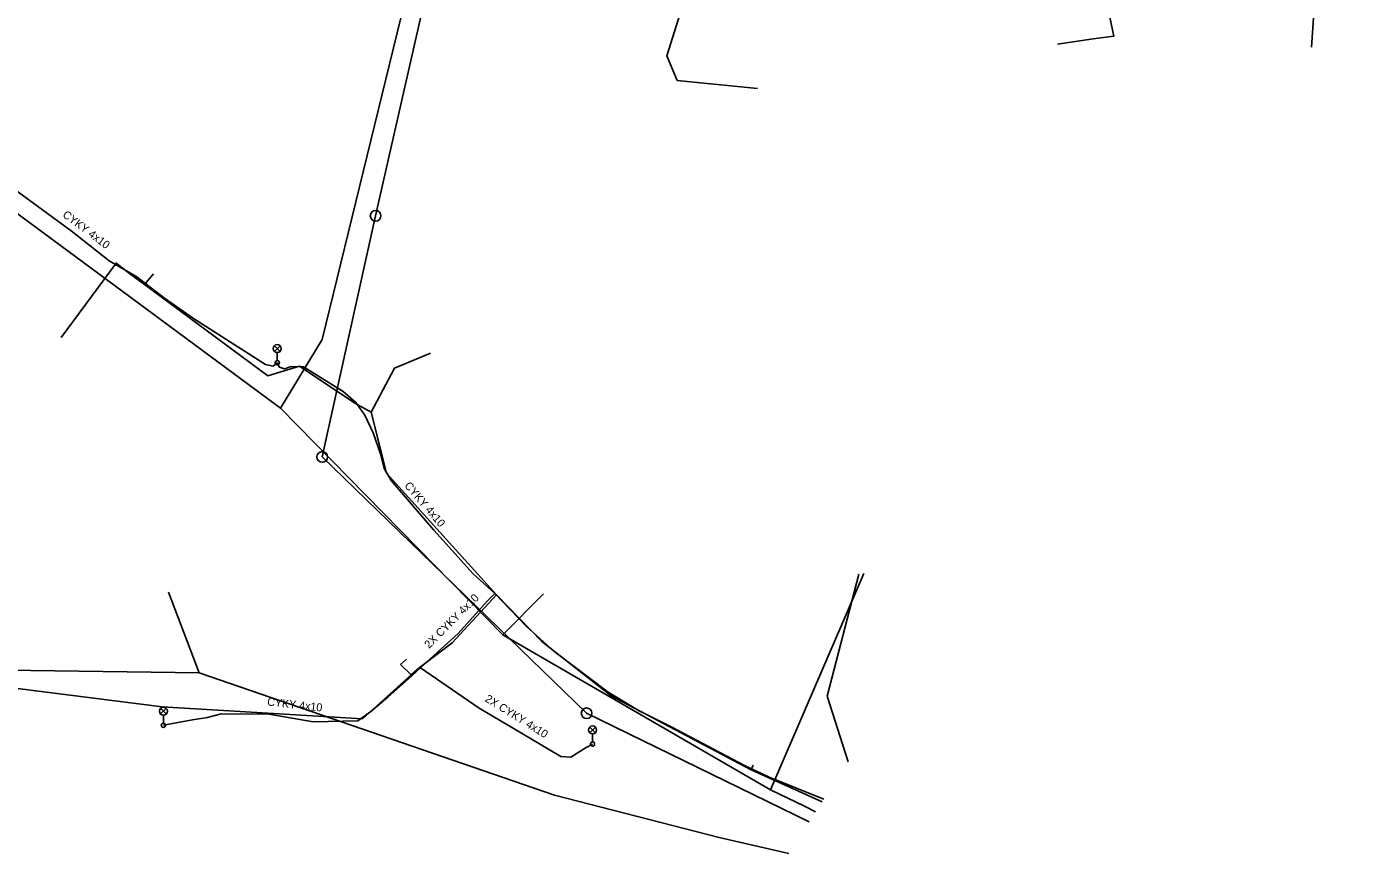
# Model space of a CAD drawing. Extents: x -737422 to -734235, y -1145631 to -1142623.
# Drawn here: x -736944.2 to -736819.2, y -1144919.8 to -1144842.3 of the extents above; entities that cross this region are included whole.
import ezdxf

# ---------------------------------------------------------------- set-up
doc = ezdxf.new("R2010")
doc.units = 0
for name, color, linetype in [('Vrstva 1', 7, 'Continuous'), ('Vrstva 19', 7, 'Continuous'), ('Vrstva 20', 7, 'Continuous'), ('Vrstva 34', 7, 'Continuous'), ('Vrstva 40', 7, 'Continuous'), ('Vrstva 41', 7, 'Continuous'), ('Vrstva 44', 7, 'Continuous'), ('Vrstva 48', 7, 'Continuous')]:
    doc.layers.add(name, color=color, linetype=linetype)

# ---------------------------------------------------------------- blocks, each defined once
blk = doc.blocks.new('6.200')
at = {"layer": 'Vrstva 1'}
blk.add_circle((0, 0), 1, dxfattribs=at)
blk = doc.blocks.new('6.560')
at = {"layer": 'Vrstva 1'}
for p, q in [((-0.528, 2.124), (0.528, 3.18)), ((0.544, 2.13), (-0.512, 3.188)), ((0, 1.9), (0, 0.4))]:
    blk.add_line(p, q, dxfattribs=at)
for centre, radius in [((0, 2.65), 0.75), ((0, 0), 0.4)]:
    blk.add_circle(centre, radius, dxfattribs=at)

msp = doc.modelspace()

# ---------------------------------------------------------------- linework, layer by layer
at = {"layer": 'Vrstva 1'}
for points in [[(-736875.7, -1144848.09), (-736883.22, -1144847.33), (-736884.18, -1144845.02), (-736876.97, -1144822.08), (-736876.39, -1144819.98), (-736870.6, -1144821.45), (-736863.03, -1144825.56), (-736858.71, -1144827.79), (-736849.16, -1144832.72), (-736846.17, -1144833.48), (-736843.72, -1144834.58)], [(-736843.72, -1144834.58), (-736843.93, -1144835.43), (-736842.3, -1144843.17), (-736844.25, -1144843.44), (-736847.59, -1144843.92)], [(-736823.778, -1144844.217), (-736823.57, -1144841.04)], [(-736933.14, -1144866.48), (-736934.55, -1144865.44), (-736935.81, -1144864.47), (-736940.97, -1144871.44)], [(-736933.14, -1144866.48), (-736932.31, -1144865.46)], [(-736933.14, -1144866.48), (-736921.6, -1144875.04), (-736918.63, -1144874.14), (-736913.42, -1144877.6), (-736911.92, -1144878.46)], [(-736906.33, -1144872.92), (-736909.73, -1144874.33), (-736911.92, -1144878.46)], [(-736911.92, -1144878.46), (-736910.46, -1144884.17), (-736900.17, -1144895.59)], [(-737067.53, -1144887.62), (-737044.25, -1144894.43), (-737027.71, -1144897.68), (-737007.28, -1144902), (-736994.61, -1144902.63), (-736992.92, -1144905.3), (-736982.45, -1144906.21), (-736972.84, -1144905.66), (-736969.04, -1144902.9), (-736965.15, -1144901.63), (-736959.3, -1144902.83), (-736956.18, -1144902.96), (-736931.49, -1144906.08), (-736912.72, -1144907.2), (-736908.17, -1144903.08)], [(-736866.19, -1144893.65), (-736869.17, -1144905.1), (-736867.202, -1144911.242)], [(-736928.01, -1144902.9), (-736930.89, -1144895.33)], [(-736900.17, -1144895.59), (-736904.3, -1144900.08), (-736907.41, -1144902.42)], [(-736876.28, -1144912.01), (-736889.41, -1144905.05), (-736895.9, -1144899.97), (-736900.17, -1144895.59)], [(-736928.01, -1144902.9), (-736959.61, -1144902.46), (-736964.22, -1144901.19)], [(-736909.15, -1144902.11), (-736908.59, -1144901.623)], [(-736908.17, -1144903.08), (-736909.15, -1144902.11)], [(-736872.766, -1144919.83), (-736879.28, -1144918.33), (-736894.72, -1144914.36), (-736928.01, -1144902.9)], [(-736907.41, -1144902.42), (-736908.17, -1144903.08)], [(-736876.28, -1144912.01), (-736876.1, -1144911.57)], [(-736876.28, -1144912.01), (-736869.641, -1144915.007)]]:
    msp.add_lwpolyline(points, dxfattribs=at)
at = {"layer": 'Vrstva 19'}
for points in [[(-736874.47, -1144913.86), (-736865.72, -1144893.59)], [(-736895.76, -1144895.49), (-736899.56, -1144899.32)]]:
    msp.add_lwpolyline(points, dxfattribs=at)
at = {"layer": 'Vrstva 20'}
for points in [[(-736920.4, -1144878.06), (-736972.09, -1144839.84), (-737043.15, -1144791.09), (-737078.91, -1144779.06), (-737081, -1144796.97)], [(-736920.4, -1144878.06), (-736916.51, -1144871.64), (-736906.66, -1144831.34), (-736899.59, -1144823.06), (-736888.63, -1144818.43), (-736854.34, -1144829.36), (-736819.202, -1144837.154)], [(-736870.249, -1144915.944), (-736871.28, -1144915.42), (-736874.47, -1144913.86), (-736899.56, -1144899.32), (-736920.4, -1144878.06)]]:
    msp.add_lwpolyline(points, dxfattribs=at)
at = {"layer": 'Vrstva 34'}
for points in [[(-736959.42, -1144847.54), (-736959.41, -1144848.11), (-736959.06, -1144848.64), (-736956.31, -1144850.37), (-736952.75, -1144852.39), (-736945.73, -1144857.24), (-736940.03, -1144861.45), (-736936.47, -1144864.25), (-736933.86, -1144865.77), (-736931.28, -1144867.75), (-736928.55, -1144869.68), (-736921.8, -1144873.97), (-736921.08, -1144874.14), (-736920.71, -1144873.81)], [(-736920.71, -1144873.81), (-736920.49, -1144874.23), (-736920.04, -1144874.38), (-736919.4, -1144874.16), (-736918.24, -1144874.19), (-736914.52, -1144876.51), (-736913.33, -1144877.53), (-736912.49, -1144878.72), (-736911.71, -1144880.38), (-736910.99, -1144882.46), (-736910.69, -1144883.72), (-736910.02, -1144884.86), (-736906.03, -1144889.52), (-736902.33, -1144893.6), (-736900.32, -1144895.45)], [(-736907.27, -1144902.43), (-736906.36, -1144901.6), (-736903.74, -1144899.22), (-736901.04, -1144896.19), (-736900.32, -1144895.45)], [(-736900.32, -1144895.45), (-736897.38, -1144898.53), (-736894.77, -1144900.86), (-736889.69, -1144904.72), (-736886.79, -1144906.45), (-736883.74, -1144908), (-736876.93, -1144911.59), (-736874.61, -1144912.67), (-736869.47, -1144914.742)], [(-736931.38, -1144907.82), (-736928.66, -1144907.3), (-736927.25, -1144907.09), (-736925.96, -1144906.73), (-736921.46, -1144906.77), (-736917.33, -1144907.49), (-736913.17, -1144907.4), (-736911.94, -1144906.51), (-736910.31, -1144905.14), (-736908.41, -1144903.47), (-736907.27, -1144902.43)], [(-736891.16, -1144909.58), (-736891.75, -1144909.89), (-736893.18, -1144910.81), (-736894.14, -1144910.75), (-736898.66, -1144908.06), (-736901.78, -1144906.21), (-736907.27, -1144902.43)]]:
    msp.add_lwpolyline(points, dxfattribs=at)
at = {"layer": 'Vrstva 40'}
for points in [[(-736911.49, -1144860.04), (-736906.81, -1144839.39), (-736905.38, -1144833.05), (-736900.7, -1144812.4)], [(-736916.49, -1144882.65), (-736911.49, -1144860.04)], [(-736891.71, -1144906.69), (-736916.49, -1144882.65)], [(-736870.851, -1144916.873), (-736891.71, -1144906.69)]]:
    msp.add_lwpolyline(points, dxfattribs=at)

# ---------------------------------------------------------------- block references
at = {"layer": 'Vrstva 41', "xscale": 0.5, "yscale": 0.5}
for p in [(-736911.49, -1144860.04), (-736916.49, -1144882.65), (-736891.71, -1144906.69)]:
    msp.add_blockref('6.200', p, dxfattribs=at)
at = {"layer": 'Vrstva 44', "xscale": 0.5, "yscale": 0.5}
for p in [(-736920.71, -1144873.81), (-736931.38, -1144907.82), (-736891.16, -1144909.58)]:
    msp.add_blockref('6.560', p, dxfattribs=at)

# ---------------------------------------------------------------- texts
at = {"layer": 'Vrstva 48'}
for s, rotation, p in [('CYKY 4x10', 322.995, (-736940.89, -1144860.07)), ('CYKY 4x10', 310.655, (-736908.84, -1144885.37)), ('2X CYKY 4x10', 44.917, (-736906.48, -1144900.67)), ('CYKY 4x10', 353.614, (-736921.68, -1144905.96)), ('2X CYKY 4x10', 328.121, (-736901.31, -1144905.52))]:
    msp.add_text(s, height=0.75, rotation=rotation, dxfattribs=at).set_placement(p)

doc.saveas('drawing.dxf')
